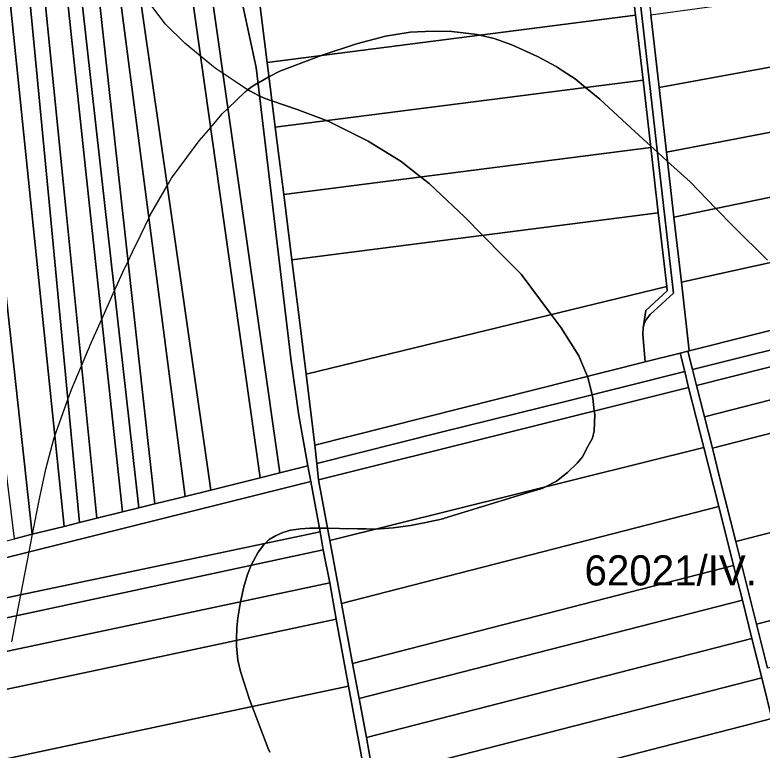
# Model space of a CAD drawing. Extents: x -521939 to -516426, y -1197857 to -1189551.
# Drawn here: x -519779.4 to -519407.3, y -1192749.7 to -1192383.7 of the extents above; entities that cross this region are included whole.
import ezdxf

# ---------------------------------------------------------------- set-up
doc = ezdxf.new("R2010")
doc.units = 0
for name, color, linetype in [('95560013', 7, 'Continuous'), ('95610013', 7, 'Continuous'), ('95640013', 7, 'Continuous'), ('95660013', 7, 'Continuous')]:
    doc.layers.add(name, color=color, linetype=linetype)

msp = doc.modelspace()

# ---------------------------------------------------------------- linework, layer by layer
at = {"layer": '95560013'}
for points in [[(-519702.6, -1192293.19), (-519692.96, -1192292.11), (-519667.58, -1192470.81), (-519647.57, -1192611.7), (-519657.37, -1192614.13), (-519677.53, -1192471.08)], [(-519677.59, -1192290.38), (-519669.04, -1192364.21), (-519659.3, -1192409.79), (-519641.95, -1192556.01), (-519638.12, -1192583.1), (-519633.56, -1192608.18), (-519647.57, -1192611.7), (-519667.58, -1192470.81), (-519692.96, -1192292.11)], [(-519737.18, -1192297.09), (-519728.36, -1192296.09), (-519702.96, -1192473.12), (-519681.85, -1192620.25), (-519694.74, -1192623.42), (-519714.11, -1192474.48)], [(-519728.36, -1192296.09), (-519702.6, -1192293.19), (-519677.53, -1192471.08), (-519657.37, -1192614.13), (-519681.85, -1192620.25), (-519702.96, -1192473.12)], [(-519761.47, -1192299.88), (-519742.78, -1192474.15), (-519725.94, -1192631.17), (-519738.69, -1192634.33), (-519754.15, -1192479.92), (-519772.06, -1192301.04)], [(-519754.83, -1192299.07), (-519734.83, -1192477), (-519717.73, -1192629.13), (-519725.94, -1192631.17), (-519742.78, -1192474.15), (-519761.47, -1192299.88)], [(-519746.04, -1192298.08), (-519725.99, -1192479.8), (-519709.73, -1192627.17), (-519717.73, -1192629.13), (-519734.83, -1192477), (-519754.83, -1192299.07)], [(-519737.18, -1192297.09), (-519714.11, -1192474.48), (-519694.74, -1192623.42), (-519709.73, -1192627.17), (-519725.99, -1192479.8), (-519746.04, -1192298.08)], [(-519789.59, -1192302.99), (-519769.9, -1192493.34), (-519754.9, -1192638.35), (-519770.8, -1192642.27), (-519788.33, -1192484.12), (-519808.17, -1192305.13)], [(-519747.21, -1192636.42), (-519754.9, -1192638.35), (-519769.9, -1192493.34), (-519789.59, -1192302.99), (-519779.22, -1192301.82), (-519762.31, -1192478.58)], [(-519738.69, -1192634.33), (-519747.21, -1192636.42), (-519762.31, -1192478.58), (-519779.22, -1192301.82), (-519772.06, -1192301.04), (-519754.15, -1192479.92)], [(-519808.17, -1192305.13), (-519788.33, -1192484.12), (-519770.8, -1192642.27), (-519779.66, -1192644.53), (-519799.43, -1192484.12), (-519821.31, -1192306.59)], [(-519653.89, -1192407.3), (-519657.72, -1192376.94), (-519473.84, -1192353.4), (-519470.34, -1192383.8)], [(-519272, -1192385.55), (-519458.66, -1192419.73), (-519462.82, -1192383.56), (-519313.5, -1192363.06), (-519274.55, -1192357.98)], [(-519466.62, -1192416.16), (-519649.8, -1192439.62), (-519653.89, -1192407.3), (-519470.34, -1192383.8)], [(-519458.66, -1192419.73), (-519272, -1192385.55), (-519270.57, -1192401.05), (-519268.72, -1192416.34), (-519454.95, -1192452)], [(-519645.59, -1192473.02), (-519647.85, -1192455.08), (-519649.8, -1192439.62), (-519466.62, -1192416.16), (-519462.78, -1192449.62)], [(-519263.91, -1192445.66), (-519451.24, -1192484.3), (-519454.95, -1192452), (-519268.72, -1192416.34), (-519268.03, -1192422.01)], [(-519451.24, -1192484.3), (-519263.91, -1192445.66), (-519260.27, -1192466.51), (-519260.21, -1192475.38), (-519447.51, -1192516.68)], [(-519459.02, -1192482.29), (-519641.48, -1192505.65), (-519645.59, -1192473.02), (-519462.78, -1192449.62)], [(-519447.51, -1192516.68), (-519260.21, -1192475.38), (-519260.01, -1192504.83), (-519443.57, -1192550.97)], [(-519641.48, -1192505.65), (-519459.02, -1192482.29), (-519454.81, -1192518.88), (-519634.4, -1192562.54), (-519637.53, -1192537.04)], [(-519634.4, -1192562.54), (-519454.81, -1192518.88), (-519454.57, -1192520.99), (-519465.2, -1192530.8), (-519466.59, -1192539.48), (-519466.7, -1192542.72), (-519465.49, -1192556.48), (-519630.06, -1192597.85)], [(-519440.02, -1192568.15), (-519372.23, -1192551.03), (-519253.11, -1192522.25), (-519250.78, -1192536.34), (-519435.96, -1192583.85)], [(-519245.81, -1192551.56), (-519432.1, -1192599.37), (-519435.96, -1192583.85), (-519250.78, -1192536.34), (-519249.45, -1192543.81), (-519248.82, -1192546.17), (-519246.64, -1192545.7)], [(-519432.1, -1192599.37), (-519245.81, -1192551.56), (-519239.7, -1192594.73), (-519239.08, -1192599.36), (-519420.42, -1192645.86), (-519428.49, -1192613.78)], [(-519443.92, -1192569.11), (-519436.29, -1192599.1), (-519622.59, -1192645.36), (-519628.19, -1192615.14)], [(-519622.59, -1192645.36), (-519436.29, -1192599.1), (-519428.91, -1192628.48), (-519616.78, -1192676.72)], [(-519233.4, -1192641.79), (-519410.05, -1192687.11), (-519420.42, -1192645.86), (-519239.08, -1192599.36)], [(-519850.15, -1192660.66), (-519848.77, -1192670.05), (-519674.6, -1192626.61), (-519632.14, -1192616.02), (-519627.48, -1192641.08), (-519715.74, -1192659.63), (-519893.83, -1192697.06), (-519883.59, -1192673.01), (-519866.95, -1192634.05), (-519859.02, -1192613.05)], [(-519616.78, -1192676.72), (-519428.91, -1192628.48), (-519421.53, -1192657.87), (-519611.3, -1192706.56)], [(-519715.74, -1192659.63), (-519627.48, -1192641.08), (-519625.92, -1192650.01), (-519724.72, -1192671.23), (-519899.04, -1192708.67), (-519893.83, -1192697.06)], [(-519410.05, -1192687.11), (-519233.4, -1192641.79), (-519230.4, -1192664.21), (-519404.56, -1192708.94)], [(-519899.04, -1192708.67), (-519724.72, -1192671.23), (-519625.92, -1192650.01), (-519622.66, -1192666.44), (-519726.69, -1192688.48), (-519903.22, -1192725.88), (-519902.42, -1192715.87)], [(-519611.3, -1192706.56), (-519421.53, -1192657.87), (-519417.16, -1192675.14), (-519608.05, -1192724.09)], [(-519889.94, -1192741.9), (-519897, -1192736.11), (-519903.22, -1192725.88), (-519726.69, -1192688.48), (-519622.66, -1192666.44), (-519619.47, -1192684.56), (-519712.96, -1192704.38)], [(-519608.05, -1192724.09), (-519417.16, -1192675.14), (-519412.38, -1192694.25), (-519604.4, -1192743.51)], [(-519613.24, -1192717.85), (-519676.82, -1192731.35), (-519853.29, -1192768.82), (-519889.94, -1192741.9), (-519712.96, -1192704.38), (-519619.47, -1192684.56)], [(-519412.38, -1192694.25), (-519407.47, -1192713.71), (-519600.82, -1192763.32), (-519604.4, -1192743.51)], [(-519407.47, -1192713.71), (-519402.4, -1192733.96), (-519417.77, -1192737.92), (-519596.97, -1192784.09), (-519600.82, -1192763.32)], [(-519605.13, -1192761.84), (-519798.31, -1192802.61), (-519853.29, -1192768.82), (-519676.82, -1192731.35), (-519613.24, -1192717.85)], [(-519596.97, -1192784.09), (-519417.77, -1192737.92), (-519402.4, -1192733.96), (-519395.16, -1192762.71), (-519416.57, -1192768.19), (-519591.64, -1192813)]]:
    msp.add_lwpolyline(points, close=True, dxfattribs=at)
at = {"layer": '95610013'}
msp.add_lwpolyline([(-519481.53, -1192286.56), (-519484.92, -1192257.05), (-519485.83, -1192249.1), (-519482.85, -1192248.8), (-519467.13, -1192385.47), (-519451.42, -1192522.16), (-519463.02, -1192532.88), (-519464.88, -1192535.1), (-519466.06, -1192537.46), (-519466.59, -1192539.48), (-519465.2, -1192530.8), (-519454.57, -1192520.99), (-519454.81, -1192518.88), (-519459.02, -1192482.29), (-519462.78, -1192449.62), (-519466.62, -1192416.16), (-519470.34, -1192383.8), (-519473.84, -1192353.4), (-519477.71, -1192319.71), (-519479.62, -1192303.13)], close=True, dxfattribs=at)
at = {"layer": '95640013'}
for points in [[(-519465.49, -1192556.48), (-519466.7, -1192542.72), (-519466.59, -1192539.48), (-519466.06, -1192537.46), (-519464.88, -1192535.1), (-519463.02, -1192532.88), (-519451.42, -1192522.16), (-519467.13, -1192385.47), (-519482.85, -1192248.8), (-519478.37, -1192248.37), (-519477.47, -1192256.17), (-519473.55, -1192290.29), (-519471.72, -1192306.18), (-519462.82, -1192383.56), (-519458.66, -1192419.73), (-519454.95, -1192452), (-519451.24, -1192484.3), (-519447.51, -1192516.68), (-519443.57, -1192550.97), (-519444.23, -1192551.14), (-519445.03, -1192551.34), (-519448.11, -1192552.11)], [(-519444.23, -1192551.14), (-519443.57, -1192550.97), (-519260.01, -1192504.83), (-519254.84, -1192503.78), (-519255.72, -1192514.6), (-519374.15, -1192543.27), (-519441.93, -1192560.28)], [(-519441.93, -1192560.28), (-519374.15, -1192543.27), (-519255.72, -1192514.6), (-519253.11, -1192522.25), (-519372.23, -1192551.03), (-519440.02, -1192568.15)], [(-519504.63, -1192575.99), (-519567.24, -1192591.51), (-519629.07, -1192607.05), (-519630.06, -1192597.85), (-519465.49, -1192556.48), (-519448.11, -1192552.11), (-519445.81, -1192561.26)], [(-519504.63, -1192575.99), (-519445.81, -1192561.26), (-519443.92, -1192569.11), (-519628.19, -1192615.14), (-519629.07, -1192607.05), (-519567.24, -1192591.51)], [(-519633.56, -1192608.18), (-519632.14, -1192616.02), (-519674.6, -1192626.61), (-519848.77, -1192670.05), (-519850.15, -1192660.66), (-519844.86, -1192660.14), (-519834.11, -1192657.91), (-519820.29, -1192654.59), (-519809.53, -1192651.89), (-519788.96, -1192646.84), (-519779.66, -1192644.53), (-519770.8, -1192642.27), (-519754.9, -1192638.35), (-519747.21, -1192636.42), (-519738.69, -1192634.33), (-519725.94, -1192631.17), (-519717.73, -1192629.13), (-519709.73, -1192627.17), (-519694.74, -1192623.42), (-519681.85, -1192620.25), (-519657.37, -1192614.13), (-519647.57, -1192611.7)]]:
    msp.add_lwpolyline(points, close=True, dxfattribs=at)
for points in [[(-519605.13, -1192761.84), (-519613.24, -1192717.85), (-519619.47, -1192684.56), (-519622.66, -1192666.44), (-519625.92, -1192650.01), (-519627.48, -1192641.08), (-519632.14, -1192616.02), (-519633.56, -1192608.18), (-519638.12, -1192583.1), (-519641.95, -1192556.01), (-519659.3, -1192409.79), (-519669.04, -1192364.21)], [(-519657.72, -1192376.94), (-519653.89, -1192407.3), (-519649.8, -1192439.62), (-519647.85, -1192455.08), (-519645.59, -1192473.02), (-519641.48, -1192505.65), (-519637.53, -1192537.04), (-519634.4, -1192562.54), (-519630.06, -1192597.85), (-519629.07, -1192607.05), (-519628.19, -1192615.14), (-519622.59, -1192645.36), (-519616.78, -1192676.72), (-519611.3, -1192706.56), (-519608.05, -1192724.09), (-519604.4, -1192743.51), (-519600.82, -1192763.32)], [(-519402.4, -1192733.96), (-519407.47, -1192713.71), (-519412.38, -1192694.25), (-519417.16, -1192675.14), (-519421.53, -1192657.87), (-519428.91, -1192628.48), (-519436.29, -1192599.1), (-519443.92, -1192569.11), (-519445.81, -1192561.26), (-519448.11, -1192552.11), (-519445.03, -1192551.34), (-519444.23, -1192551.14), (-519441.93, -1192560.28), (-519440.02, -1192568.15), (-519435.96, -1192583.85), (-519432.1, -1192599.37), (-519428.49, -1192613.78), (-519420.42, -1192645.86), (-519410.05, -1192687.11), (-519404.56, -1192708.94)]]:
    msp.add_lwpolyline(points, dxfattribs=at)
at = {"layer": '95660013'}
for points in [[(-519780.95, -1192695.84), (-519778.44, -1192682.77), (-519776.44, -1192672.39), (-519772.33, -1192650.98), (-519770.65, -1192642.23), (-519767.27, -1192624.67), (-519764.02, -1192609.83), (-519760.08, -1192594.77), (-519759.56, -1192593.31), (-519753.07, -1192575.2), (-519751.27, -1192570.19), (-519746.3, -1192558.34), (-519741.54, -1192547.01), (-519736.24, -1192535.16), (-519729.89, -1192520.97), (-519725.77, -1192511.77), (-519723.08, -1192506.2), (-519720.87, -1192501.63), (-519716.59, -1192492.79), (-519712.76, -1192484.88), (-519711.86, -1192483.03), (-519703.59, -1192468.7), (-519701.43, -1192464.95), (-519693.82, -1192454.62), (-519687.76, -1192446.4), (-519681.96, -1192439.67), (-519676.16, -1192432.95), (-519673.34, -1192430.23), (-519664.79, -1192421.96), (-519663.69, -1192420.9), (-519669.82, -1192416.81), (-519675.81, -1192412.82), (-519679.68, -1192410.24), (-519686.96, -1192404.19), (-519694.75, -1192397.72), (-519704.49, -1192388.21), (-519714.46, -1192375)], [(-519404.63, -1192505.75), (-519421.55, -1192489.06), (-519430.38, -1192480), (-519443.23, -1192466.8), (-519454.42, -1192456.58), (-519459.49, -1192451.96), (-519462.87, -1192448.88), (-519472.55, -1192440.03), (-519488.2, -1192425.65), (-519495.29, -1192419.83), (-519500.49, -1192415.57), (-519506.41, -1192411.62), (-519509.87, -1192409.31), (-519519.26, -1192404.44), (-519532.01, -1192398.64), (-519540.82, -1192395.4), (-519547.89, -1192393.73), (-519549.17, -1192393.43), (-519561.8, -1192391.92), (-519571.42, -1192391.69), (-519582.67, -1192392.27), (-519594.84, -1192394.24), (-519609.33, -1192398.07), (-519626.36, -1192403.78), (-519629.03, -1192404.67), (-519647.46, -1192411.74), (-519652.98, -1192414.45), (-519653.37, -1192414.64), (-519658.14, -1192417.42), (-519658.38, -1192417.56), (-519660.33, -1192418.7), (-519663.69, -1192420.9), (-519669.82, -1192416.81), (-519675.81, -1192412.82), (-519679.68, -1192410.24), (-519686.96, -1192404.19), (-519694.75, -1192397.72), (-519704.49, -1192388.21), (-519714.46, -1192375)], [(-519652.46, -1192750.83), (-519653.26, -1192748.94), (-519660.47, -1192730.15), (-519660.97, -1192728.85), (-519661.28, -1192728.05), (-519662.65, -1192724.49), (-519667.17, -1192710.58), (-519668.44, -1192704.88), (-519669.14, -1192698.06), (-519669.14, -1192695.09), (-519669.14, -1192692.96), (-519669.13, -1192692.79), (-519669.11, -1192692.55), (-519669.01, -1192690.69), (-519668.91, -1192688.78), (-519668.44, -1192683.92), (-519667.04, -1192675.84), (-519666.93, -1192675.22), (-519665.43, -1192668.5), (-519663.57, -1192662.36), (-519661.76, -1192657.71), (-519661.72, -1192657.6), (-519658.24, -1192651.23), (-519655.69, -1192647.75), (-519654.75, -1192646.81), (-519652.79, -1192644.85), (-519649.66, -1192643), (-519646.07, -1192641.38), (-519642.13, -1192640.22), (-519639.58, -1192639.85), (-519637.26, -1192639.52), (-519632.51, -1192639.17), (-519627.84, -1192639.17), (-519625.21, -1192639.17), (-519623.73, -1192639.2), (-519617.75, -1192639.33), (-519608.69, -1192639.52), (-519604.46, -1192639.61), (-519600.34, -1192639.7), (-519599.62, -1192639.66), (-519591.07, -1192639.13), (-519582.49, -1192637.9), (-519573.92, -1192636.28), (-519571.75, -1192635.78), (-519568.42, -1192635.02), (-519565.8, -1192634.42), (-519565.48, -1192634.32), (-519528.71, -1192622.95), (-519523.8, -1192621.5), (-519516.89, -1192619.47), (-519515.57, -1192618.79), (-519509.7, -1192615.76), (-519504.25, -1192611.47), (-519499.39, -1192606.85), (-519498.45, -1192605.69), (-519496.83, -1192603.71), (-519494.05, -1192598.61), (-519491.85, -1192594.43), (-519490.92, -1192590.72), (-519490.69, -1192582.61), (-519490.89, -1192580.84), (-519491.62, -1192574.5), (-519492.02, -1192572.83), (-519493.94, -1192564.76), (-519494.36, -1192563.74), (-519497.09, -1192557.03), (-519497.38, -1192556.32), (-519498.57, -1192553.4), (-519502.61, -1192547.03), (-519507.38, -1192539.49), (-519512.34, -1192532.87), (-519517.64, -1192525.78), (-519527.32, -1192512.83), (-519536.12, -1192503.89), (-519546.37, -1192493.47), (-519555.37, -1192484.32), (-519573.22, -1192467.63), (-519577.47, -1192464.3), (-519587.13, -1192456.73), (-519603.59, -1192446.53), (-519623.18, -1192436.68), (-519624.1, -1192436.33), (-519624.28, -1192436.26), (-519638.94, -1192430.77), (-519651.46, -1192426.51), (-519655.29, -1192425.2), (-519657.61, -1192424.01), (-519658.14, -1192423.74), (-519662.48, -1192421.52), (-519663.69, -1192420.9), (-519660.33, -1192418.7), (-519658.38, -1192417.56), (-519658.14, -1192417.42), (-519653.37, -1192414.64), (-519652.98, -1192414.45), (-519647.46, -1192411.74), (-519629.03, -1192404.67), (-519626.36, -1192403.78), (-519609.33, -1192398.07), (-519594.84, -1192394.24), (-519582.67, -1192392.27), (-519571.42, -1192391.69), (-519561.8, -1192391.92), (-519549.17, -1192393.43), (-519547.89, -1192393.73), (-519540.82, -1192395.4), (-519532.01, -1192398.64), (-519519.26, -1192404.44), (-519509.87, -1192409.31), (-519506.41, -1192411.62), (-519500.49, -1192415.57), (-519495.29, -1192419.83), (-519488.2, -1192425.65), (-519472.55, -1192440.03), (-519462.87, -1192448.88), (-519459.49, -1192451.96), (-519454.42, -1192456.58), (-519443.23, -1192466.8), (-519430.38, -1192480), (-519421.55, -1192489.06), (-519404.63, -1192505.75)], [(-519780.95, -1192695.84), (-519778.44, -1192682.77), (-519776.44, -1192672.39), (-519772.33, -1192650.98), (-519770.65, -1192642.23), (-519767.27, -1192624.67), (-519764.02, -1192609.83), (-519760.08, -1192594.77), (-519759.56, -1192593.31), (-519753.07, -1192575.2), (-519751.27, -1192570.19), (-519746.3, -1192558.34), (-519741.54, -1192547.01), (-519736.24, -1192535.16), (-519729.89, -1192520.97), (-519725.77, -1192511.77), (-519723.08, -1192506.2), (-519720.87, -1192501.63), (-519716.59, -1192492.79), (-519712.76, -1192484.88), (-519711.86, -1192483.03), (-519703.59, -1192468.7), (-519701.43, -1192464.95), (-519693.82, -1192454.62), (-519687.76, -1192446.4), (-519681.96, -1192439.67), (-519676.16, -1192432.95), (-519673.34, -1192430.23), (-519664.79, -1192421.96), (-519663.69, -1192420.9), (-519662.48, -1192421.52), (-519658.14, -1192423.74), (-519657.61, -1192424.01), (-519655.29, -1192425.2), (-519651.46, -1192426.51), (-519638.94, -1192430.77), (-519624.28, -1192436.26), (-519624.1, -1192436.33), (-519623.18, -1192436.68), (-519603.59, -1192446.53), (-519587.13, -1192456.73), (-519577.47, -1192464.3), (-519573.22, -1192467.63), (-519555.37, -1192484.32), (-519546.37, -1192493.47), (-519536.12, -1192503.89), (-519527.32, -1192512.83), (-519517.64, -1192525.78), (-519512.34, -1192532.87), (-519507.38, -1192539.49), (-519502.61, -1192547.03), (-519498.57, -1192553.4), (-519497.38, -1192556.32), (-519497.09, -1192557.03), (-519494.36, -1192563.74), (-519493.94, -1192564.76), (-519492.02, -1192572.83), (-519491.62, -1192574.5), (-519490.89, -1192580.84), (-519490.69, -1192582.61), (-519490.92, -1192590.72), (-519491.85, -1192594.43), (-519494.05, -1192598.61), (-519496.83, -1192603.71), (-519498.45, -1192605.69), (-519499.39, -1192606.85), (-519504.25, -1192611.47), (-519509.7, -1192615.76), (-519515.57, -1192618.79), (-519516.89, -1192619.47), (-519523.8, -1192621.5), (-519528.71, -1192622.95), (-519565.48, -1192634.32), (-519565.8, -1192634.42), (-519568.42, -1192635.02), (-519571.75, -1192635.78), (-519573.92, -1192636.28), (-519582.49, -1192637.9), (-519591.07, -1192639.13), (-519599.62, -1192639.66), (-519600.34, -1192639.7), (-519604.46, -1192639.61), (-519608.69, -1192639.52), (-519617.75, -1192639.33), (-519623.73, -1192639.2), (-519625.21, -1192639.17), (-519627.84, -1192639.17), (-519632.51, -1192639.17), (-519637.26, -1192639.52), (-519639.58, -1192639.85), (-519642.13, -1192640.22), (-519646.07, -1192641.38), (-519649.66, -1192643), (-519652.79, -1192644.85), (-519654.75, -1192646.81), (-519655.69, -1192647.75), (-519658.24, -1192651.23), (-519661.72, -1192657.6), (-519661.76, -1192657.71), (-519663.57, -1192662.36), (-519665.43, -1192668.5), (-519666.93, -1192675.22), (-519667.04, -1192675.84), (-519668.44, -1192683.92), (-519668.91, -1192688.78), (-519669.01, -1192690.69), (-519669.11, -1192692.55), (-519669.13, -1192692.79), (-519669.14, -1192692.96), (-519669.14, -1192695.09), (-519669.14, -1192698.06), (-519668.44, -1192704.88), (-519667.17, -1192710.58), (-519662.65, -1192724.49), (-519661.28, -1192728.05), (-519660.97, -1192728.85), (-519660.47, -1192730.15), (-519653.26, -1192748.94), (-519652.46, -1192750.83)]]:
    msp.add_lwpolyline(points, dxfattribs=at)

# ---------------------------------------------------------------- texts
msp.add_text('62021/IV.', height=15, rotation=360, dxfattribs=at).set_placement((-519495.76, -1192667.76))

doc.saveas('drawing.dxf')
